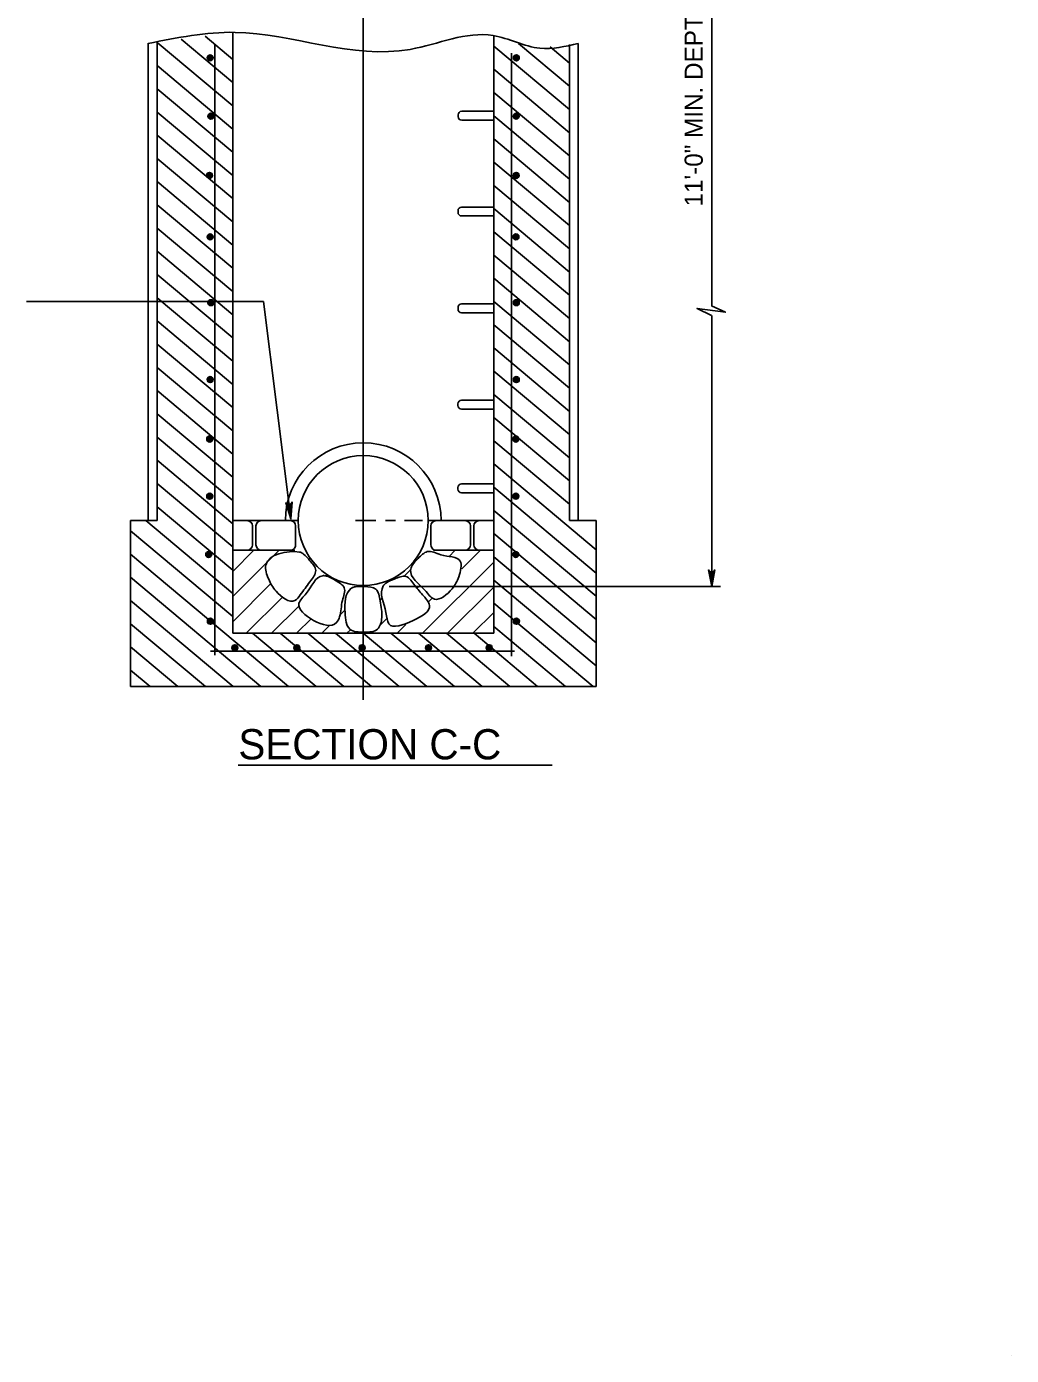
# Model space of a CAD drawing. Extents: x 0.2 to 7.1, y 1.2 to 11.2.
# Drawn here: x 3.887 to 7.142, y 1.151 to 5.546 of the extents above; entities that cross this region are included whole.
import ezdxf

# ---------------------------------------------------------------- set-up
doc = ezdxf.new("R2010")
doc.units = 0
for name, color, linetype in [('DETL-DIMS', 7, 'Continuous'), ('DETL-LINE', 7, 'Continuous'), ('DETL-NOTE', 7, 'Continuous'), ('DETL-PATT', 7, 'Continuous'), ('DETL-TITL', 7, 'Continuous'), ('TTLB-TEXT', 7, 'Continuous')]:
    doc.layers.add(name, color=color, linetype=linetype)

msp = doc.modelspace()

# ---------------------------------------------------------------- linework, layer by layer
at = {"layer": 'DETL-DIMS'}
for p, q in [((6.1514, 4.6226), (6.1514, 8.1202)), ((4.9995, 3.3192), (4.9995, 7.6411)), ((3.8867, 4.6362), (4.6704, 4.6362)), ((4.6704, 4.6362), (4.7607, 3.9177)), ((6.1514, 3.6942), (6.1514, 4.5909)), ((5.0412, 3.9121), (4.9743, 3.9121)), ((5.106, 3.9121), (5.0736, 3.9121)), ((5.1951, 3.9121), (5.1364, 3.9121)), ((5.0858, 3.6942), (6.1809, 3.6942))]:
    msp.add_line(p, q, dxfattribs=at)
for points in [[(6.1511, 4.5905), (6.1034, 4.6138), (6.1967, 4.6011), (6.1511, 4.6228)], [(4.7607, 3.9177), (4.7437, 3.9708), (4.7471, 3.967), (4.751, 3.9653), (4.7547, 3.9651), (4.7583, 3.9662), (4.7617, 3.9688), (4.7641, 3.9734), (4.7607, 3.9177), (4.7617, 3.9688), (4.7583, 3.9662), (4.7607, 3.9177), (4.7547, 3.9651), (4.751, 3.9653), (4.7607, 3.9177), (4.7471, 3.967)], [(6.1514, 3.6942), (6.1412, 3.7491), (6.1441, 3.7448), (6.1478, 3.7427), (6.1514, 3.742), (6.1551, 3.7427), (6.1588, 3.7448), (6.1617, 3.7491), (6.1514, 3.6942), (6.1588, 3.7448), (6.1551, 3.7427), (6.1514, 3.6942), (6.1514, 3.742), (6.1478, 3.7427), (6.1514, 3.6942), (6.1441, 3.7448)]]:
    msp.add_lwpolyline(points, dxfattribs=at)
at = {"layer": 'DETL-LINE'}
for p, q in [((4.3181, 3.9121), (4.3181, 5.4943)), ((4.5681, 3.5395), (4.5681, 5.5263)), ((5.4309, 3.5395), (5.4309, 5.5163)), ((4.2887, 3.9121), (4.2887, 5.4905)), ((4.5093, 3.467), (4.5093, 5.4844)), ((5.4897, 3.4635), (5.4897, 5.4576)), ((5.6809, 3.9121), (5.6809, 5.4868)), ((5.7103, 3.9121), (5.7103, 5.4901)), ((5.3132, 5.2539), (5.3132, 5.248)), ((5.325, 5.2657), (5.4309, 5.2657)), ((5.325, 5.2363), (5.4309, 5.2363)), ((5.3129, 4.9372), (5.3129, 4.9313)), ((5.3247, 4.9489), (5.4309, 4.9489)), ((5.3247, 4.9195), (5.4309, 4.9195)), ((5.3129, 4.617), (5.3129, 4.6111)), ((5.3247, 4.6288), (5.4309, 4.6288)), ((5.3247, 4.5994), (5.4309, 4.5994)), ((5.3245, 4.3103), (5.4309, 4.3103)), ((5.3127, 4.2986), (5.3127, 4.2927)), ((5.3245, 4.2809), (5.4309, 4.2809)), ((5.3127, 4.0218), (5.3127, 4.0159)), ((5.3245, 4.0335), (5.4309, 4.0335)), ((5.3245, 4.0041), (5.4309, 4.0041)), ((4.2299, 3.363), (4.2299, 3.9121)), ((4.2299, 3.9121), (4.3181, 3.9121)), ((4.5681, 3.9121), (4.7817, 3.9121)), ((5.2173, 3.9121), (5.4309, 3.9121)), ((5.6809, 3.9121), (5.7691, 3.9121)), ((5.7691, 3.363), (5.7691, 3.9121)), ((4.6335, 3.8317), (4.6335, 3.8944)), ((4.6448, 3.8317), (4.6448, 3.8944)), ((4.7761, 3.8317), (4.7761, 3.8944)), ((5.2231, 3.8317), (5.2231, 3.8944)), ((5.354, 3.8317), (5.354, 3.8944)), ((5.3653, 3.8317), (5.3653, 3.8944)), ((4.5681, 3.814), (4.7737, 3.814)), ((5.232, 3.814), (5.3979, 3.814)), ((5.2822, 3.7927), (5.3035, 3.814)), ((5.3913, 3.814), (5.4309, 3.814)), ((4.5681, 3.5395), (5.4309, 3.5395)), ((4.4942, 3.4807), (5.4994, 3.4807)), ((4.2299, 3.363), (5.7691, 3.363))]:
    msp.add_line(p, q, dxfattribs=at)
for centre, radius in [((4.4936, 5.4423), 0.0098), ((4.4936, 5.4423), 0.00735), ((5.5057, 5.4423), 0.0098), ((5.5057, 5.4423), 0.00735), ((4.4936, 5.4423), 0.0049), ((4.4936, 5.4423), 0.00245), ((5.5057, 5.4423), 0.0049), ((5.5057, 5.4423), 0.00245), ((4.4961, 5.2497), 0.0098), ((4.4961, 5.2497), 0.00735), ((4.4961, 5.2497), 0.0049), ((4.4961, 5.2497), 0.00245), ((5.5053, 5.2497), 0.0098), ((5.5053, 5.2497), 0.00735), ((5.5053, 5.2497), 0.0049), ((5.5053, 5.2497), 0.00245), ((4.4912, 5.0536), 0.0098), ((4.4912, 5.0536), 0.00735), ((4.4912, 5.0536), 0.0049), ((4.4912, 5.0536), 0.00245), ((5.5052, 5.0536), 0.0098), ((5.5052, 5.0536), 0.00735), ((5.5052, 5.0536), 0.0049), ((5.5052, 5.0536), 0.00245), ((4.4936, 4.8506), 0.0098), ((4.4936, 4.8506), 0.00735), ((4.4936, 4.8506), 0.0049), ((4.4936, 4.8506), 0.00245), ((5.5045, 4.8506), 0.0098), ((5.5045, 4.8506), 0.00735), ((5.5045, 4.8506), 0.0049), ((5.5045, 4.8506), 0.00245), ((4.4961, 4.6328), 0.0098), ((4.4961, 4.6328), 0.00735), ((4.4961, 4.6328), 0.0049), ((4.4961, 4.6328), 0.00245), ((5.5057, 4.6328), 0.0098), ((5.5057, 4.6328), 0.00735), ((5.5057, 4.6328), 0.0049), ((5.5057, 4.6328), 0.00245), ((4.4937, 4.3784), 0.0098), ((4.4937, 4.3784), 0.00735), ((4.4937, 4.3784), 0.0049), ((4.4937, 4.3784), 0.00245), ((5.5056, 4.3784), 0.0098), ((5.5056, 4.3784), 0.00735), ((5.5056, 4.3784), 0.0049), ((5.5056, 4.3784), 0.00245), ((4.4921, 4.1818), 0.0098), ((4.4921, 4.1818), 0.00735), ((4.4921, 4.1818), 0.0049), ((4.4921, 4.1818), 0.00245), ((5.504, 4.1818), 0.0098), ((5.504, 4.1818), 0.00735), ((5.504, 4.1818), 0.0049), ((5.504, 4.1818), 0.00245), ((4.9995, 3.9121), 0.2148), ((4.4921, 3.9926), 0.0098), ((4.4921, 3.9926), 0.00735), ((5.504, 3.9926), 0.0098), ((5.504, 3.9926), 0.00735), ((4.4921, 3.9926), 0.0049), ((4.4921, 3.9926), 0.00245), ((5.504, 3.9926), 0.0049), ((5.504, 3.9926), 0.00245), ((4.4886, 3.7999), 0.0098), ((4.4886, 3.7999), 0.00735), ((4.4886, 3.7999), 0.0049), ((4.4886, 3.7999), 0.00245), ((5.5041, 3.7999), 0.0098), ((5.5041, 3.7999), 0.00735), ((5.5041, 3.7999), 0.0049), ((5.5041, 3.7999), 0.00245), ((4.4942, 3.5792), 0.0098), ((4.4942, 3.5792), 0.00735), ((4.4942, 3.5792), 0.0049), ((4.4942, 3.5792), 0.00245), ((5.5058, 3.5792), 0.0098), ((5.5058, 3.5792), 0.00735), ((5.5058, 3.5792), 0.0049), ((5.5058, 3.5792), 0.00245), ((4.5753, 3.4916), 0.0098), ((4.5753, 3.4916), 0.00735), ((4.5753, 3.4916), 0.0049), ((4.5753, 3.4916), 0.00245), ((4.7802, 3.4916), 0.0098), ((4.7802, 3.4916), 0.00735), ((4.7802, 3.4916), 0.0049), ((4.7802, 3.4916), 0.00245), ((4.9957, 3.4916), 0.0098), ((4.9957, 3.4916), 0.00735), ((4.9957, 3.4916), 0.0049), ((4.9957, 3.4916), 0.00245), ((5.2155, 3.4916), 0.0098), ((5.2155, 3.4916), 0.00735), ((5.2155, 3.4916), 0.0049), ((5.2155, 3.4916), 0.00245), ((5.4161, 3.4916), 0.0098), ((5.4161, 3.4916), 0.00735), ((5.4161, 3.4916), 0.0049), ((5.4161, 3.4916), 0.00245)]:
    msp.add_circle(centre, radius, dxfattribs=at)
for centre, radius, start, end in [((5.325, 5.2539), 0.0118, 90, 180), ((5.325, 5.248), 0.0118, 180, 270), ((5.3247, 4.9372), 0.0118, 90, 180), ((5.3247, 4.9313), 0.0118, 180, 270), ((5.3247, 4.617), 0.0118, 90, 180), ((5.3247, 4.6111), 0.0118, 180, 270), ((5.3245, 4.2986), 0.0118, 90, 180), ((5.3245, 4.2927), 0.0118, 180, 270), ((4.9995, 3.9121), 0.2574, 0, 180), ((5.3245, 4.0218), 0.0118, 90, 180), ((5.3245, 4.0159), 0.0118, 180, 270), ((4.6159, 3.8944), 0.0176, 0, 90), ((4.6625, 3.8944), 0.0176, 90, 180), ((4.7584, 3.8944), 0.0176, 0, 90), ((5.2408, 3.8944), 0.0176, 90, 180), ((5.3363, 3.8944), 0.0176, 0, 90), ((5.383, 3.8944), 0.0176, 90, 180), ((4.6159, 3.8317), 0.0176, 270, 0), ((4.6625, 3.8317), 0.0176, 180, 270), ((4.7584, 3.8317), 0.0176, 258.2538, 0), ((5.2408, 3.8317), 0.0176, 180, 281.7563), ((5.3363, 3.8317), 0.0176, 270, 0), ((5.383, 3.8317), 0.0176, 180, 270)]:
    msp.add_arc(centre, radius, start, end, dxfattribs=at)
for points in [[(5.7103, 5.4901), (5.5836, 5.4741), (5.4291, 5.5163), (5.1551, 5.4706), (4.5757, 5.5268), (4.2887, 5.4901)], [(4.7923, 3.8075), (4.802, 3.8016), (4.8232, 3.7795), (4.8424, 3.7474), (4.8233, 3.7099), (4.7914, 3.6661), (4.7739, 3.648), (4.7118, 3.6782), (4.687, 3.7185), (4.6773, 3.7652), (4.7886, 3.8081), (4.7918, 3.8075)], [(5.1566, 3.7535), (5.1615, 3.7638), (5.1813, 3.7871), (5.2113, 3.8095), (5.2564, 3.7988), (5.3198, 3.7784), (5.3152, 3.7266), (5.2934, 3.6866), (5.2351, 3.6524), (5.2036, 3.6817), (5.1563, 3.7498), (5.1567, 3.753)], [(4.8701, 3.7304), (4.8811, 3.7279), (4.9083, 3.7139), (4.9369, 3.6898), (4.9309, 3.648), (4.9213, 3.5942), (4.9116, 3.5749), (4.8356, 3.582), (4.7872, 3.6389), (4.8108, 3.671), (4.8663, 3.7298), (4.8696, 3.7302)], [(4.9629, 3.6903), (4.9739, 3.6934), (5.0044, 3.6937), (5.041, 3.6858), (5.0553, 3.6462), (5.061, 3.5911), (5.0466, 3.553), (5.0021, 3.5432), (4.9558, 3.5526), (4.9396, 3.6077), (4.9599, 3.6881), (4.9626, 3.69)], [(5.0675, 3.6992), (5.0762, 3.7065), (5.1039, 3.7195), (5.1405, 3.7274), (5.1699, 3.6973), (5.1997, 3.6625), (5.2184, 3.6317), (5.1642, 3.5815), (5.0843, 3.5707), (5.0747, 3.6081), (5.0657, 3.6959), (5.0674, 3.6987)]]:
    msp.add_spline(points, degree=3, dxfattribs=at)
at = {"layer": 'DETL-PATT'}
for p, q in [((4.3181, 5.4937), (4.5681, 5.2839)), ((4.3974, 5.504), (4.5681, 5.3607)), ((4.4767, 5.5142), (4.5681, 5.4375)), ((5.4309, 5.4815), (5.6809, 5.2717)), ((5.5125, 5.4897), (5.6809, 5.3485)), ((5.6175, 5.4784), (5.6809, 5.4253)), ((4.3181, 5.4169), (4.5681, 5.2071)), ((5.4309, 5.4047), (5.6809, 5.1949)), ((4.3181, 5.3401), (4.5681, 5.1304)), ((5.4309, 5.3279), (5.6809, 5.1181)), ((4.3181, 5.2633), (4.5681, 5.0536)), ((5.4309, 5.2511), (5.6809, 5.0413)), ((4.3181, 5.1866), (4.5681, 4.9768)), ((5.4309, 5.1743), (5.6809, 4.9645)), ((4.3181, 5.1098), (4.5681, 4.9)), ((5.4309, 5.0975), (5.6809, 4.8877)), ((4.3181, 5.033), (4.5681, 4.8232)), ((5.4309, 5.0207), (5.6809, 4.811)), ((4.3181, 4.9562), (4.5681, 4.7464)), ((5.4309, 4.9439), (5.6809, 4.7342)), ((4.3181, 4.8794), (4.5681, 4.6696)), ((5.4309, 4.8672), (5.6809, 4.6574)), ((4.3181, 4.8026), (4.5681, 4.5928)), ((5.4309, 4.7904), (5.6809, 4.5806)), ((4.3181, 4.7258), (4.5681, 4.516)), ((5.4309, 4.7136), (5.6809, 4.5038)), ((4.3181, 4.649), (4.5681, 4.4393)), ((5.4309, 4.6368), (5.6809, 4.427)), ((4.3181, 4.5722), (4.5681, 4.3625)), ((5.4309, 4.56), (5.6809, 4.3502)), ((4.3181, 4.4955), (4.5681, 4.2857)), ((5.4309, 4.4832), (5.6809, 4.2734)), ((4.3181, 4.4187), (4.5681, 4.2089)), ((5.4309, 4.4064), (5.6809, 4.1967)), ((4.3181, 4.3419), (4.5681, 4.1321)), ((5.4309, 4.3296), (5.6809, 4.1199)), ((4.3181, 4.2651), (4.5681, 4.0553)), ((5.4309, 4.2528), (5.6809, 4.0431)), ((4.3181, 4.1883), (4.5681, 3.9785)), ((5.4309, 4.1761), (5.6809, 3.9663)), ((4.3181, 4.1115), (4.5681, 3.9017)), ((5.4309, 4.0993), (5.7691, 3.8155)), ((4.3181, 4.0347), (4.5681, 3.8249)), ((5.4309, 4.0225), (5.7691, 3.7387)), ((4.3181, 3.9579), (4.5681, 3.7482)), ((4.2813, 3.9121), (4.5681, 3.6714)), ((5.4309, 3.9457), (5.7691, 3.6619)), ((4.2299, 3.8784), (4.5681, 3.5946)), ((5.4309, 3.8689), (5.7691, 3.5851)), ((4.2299, 3.8016), (4.7525, 3.363)), ((4.5681, 3.661), (4.7212, 3.814)), ((4.5681, 3.7441), (4.638, 3.814)), ((4.6724, 3.814), (4.6795, 3.814)), ((5.3194, 3.814), (5.3266, 3.814)), ((5.3252, 3.7526), (5.3867, 3.814)), ((5.4309, 3.7921), (5.7691, 3.5083)), ((5.1357, 3.7294), (5.1564, 3.7501)), ((5.1954, 3.5395), (5.4309, 3.775)), ((4.2299, 3.7248), (4.661, 3.363)), ((4.5681, 3.5778), (4.6942, 3.7039)), ((5.1778, 3.6883), (5.1875, 3.698)), ((5.2786, 3.5395), (5.4309, 3.6918)), ((5.4309, 3.7153), (5.7691, 3.4315)), ((4.2299, 3.648), (4.5695, 3.363)), ((4.613, 3.5395), (4.7325, 3.659)), ((5.0549, 3.6486), (5.0623, 3.656)), ((5.2147, 3.6421), (5.2288, 3.6562)), ((4.6962, 3.5395), (4.7863, 3.6296)), ((4.9222, 3.5991), (4.9396, 3.6165)), ((5.3617, 3.5395), (5.4309, 3.6086)), ((5.4309, 3.6385), (5.7592, 3.363)), ((4.2299, 3.5712), (4.478, 3.363)), ((4.7794, 3.5395), (4.828, 3.5881)), ((4.8626, 3.5395), (4.8867, 3.5636)), ((5.0575, 3.568), (5.0779, 3.5885)), ((5.1122, 3.5395), (5.1409, 3.5683)), ((5.4309, 3.5617), (5.6677, 3.363)), ((4.6337, 3.5395), (4.844, 3.363)), ((4.7252, 3.5395), (4.9356, 3.363)), ((4.8168, 3.5395), (5.0271, 3.363)), ((4.9083, 3.5395), (5.1186, 3.363)), ((4.9458, 3.5395), (4.9574, 3.5511)), ((4.9998, 3.5395), (5.2101, 3.363)), ((5.0913, 3.5395), (5.3016, 3.363)), ((5.1828, 3.5395), (5.3931, 3.363)), ((5.2743, 3.5395), (5.4846, 3.363)), ((5.3658, 3.5395), (5.5761, 3.363)), ((4.2299, 3.4945), (4.3865, 3.363)), ((4.2299, 3.4177), (4.295, 3.363))]:
    msp.add_line(p, q, dxfattribs=at)
at = {"layer": 'DETL-TITL'}
msp.add_line((4.5863, 3.1038), (5.6242, 3.1038), dxfattribs=at)
at = {"layer": 'TTLB-TEXT'}
msp.add_line((7.1422, 1.1512), (7.1422, 1.1512), dxfattribs=at)

# ---------------------------------------------------------------- texts
at = {"layer": 'DETL-NOTE'}
msp.add_text('11\'-0" MIN. DEPTH PAYMENT', height=0.06, rotation=90, dxfattribs=at).set_placement((6.122, 4.9509))
at = {"layer": 'DETL-TITL'}
msp.add_text('SECTION C-C', height=0.1, dxfattribs=at).set_placement((4.5867, 3.1224))

doc.saveas('drawing.dxf')
